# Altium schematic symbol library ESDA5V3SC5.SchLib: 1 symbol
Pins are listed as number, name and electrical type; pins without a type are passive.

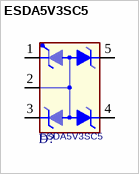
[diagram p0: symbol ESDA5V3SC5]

## ESDA5V3SC5
designator D?
footprint ST_SOT23-5L
pins: 1, 2, 3, 4, 5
